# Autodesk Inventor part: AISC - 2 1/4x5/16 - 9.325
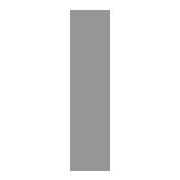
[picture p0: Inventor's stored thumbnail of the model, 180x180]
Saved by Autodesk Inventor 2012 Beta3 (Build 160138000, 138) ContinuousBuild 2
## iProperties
IsCustomPart: 1
Created: 2010-11
Part Number: AISC - 2 1/4x5/16 - 9.325
Material: Steel, Mild
Description: Flat Bar Steel
Document SubType Name: Modeling
Standard: ANSI
Designer: Beta-8540w
Standards Organization: ANSI
Language: en-US
Size Designation: 2 1/4x5/16
Categories: <MemberInstance><Categories><Category DisplayName="Structural Shapes" InternalName="089c4875-fa83-4c05-b084-43b9cc11f5ed" Mnemonic="GRDR"><CategoryParameter Dis
Stock Number: 2 1/4x5/16
Density: 7.86 g/cm^3
_CCFamilyMember: 149
_CCFamilyDisplayName: ANSI AISC (Rectangular) - Flat Bar Steel
_FrameMemberDoc: Frame Member File
_Version: 15.0.0
_GetPNFromCC: 1
G_L: 9.325 in
G_W: 0.313 in
G_H: 2.250 in
Author: Beta-8540w
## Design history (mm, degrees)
node "Start plane"
node "End plane"
node "Driven Length"
  sketch "Sketch3"
    geometry: L1 (0, 0)-(10, 0) reference
    constraints: 2 end point, 1 horizontal
  workplane "Work Plane3"
  sketch "Sketch4"
    geometry: L1 (-2, 0)-(12, 0) reference; L2 (-40.005, 236.864)-(40.005, 236.864) reference
    dimensions: "d9" = 236.86413 distance between parallel lines of L1 L2 (derived)
sketch "Sweep Path"
  geometry: L1 through (25.4, 40.279) direction (1, 0); L2 through (112.121, 127) direction (1, 0); 8 other entities
  constraints: 10 horizontal
node "Orientation Work Plane"
feature "Body" dims "d10" = 0
body "Solid1"
sketch "Sketch"
  geometry: L1 (3.969, -28.575)-(-3.969, -28.575); L2 (-3.969, -28.575)-(-3.969, 28.575); L3 (-3.969, 28.575)-(3.969, 28.575); L4 (3.969, 28.575)-(3.969, -28.575); L5 (-6, 0)-(8, 0); L6 (0, -30)-(0, 40); L7 (0, 54)-(0, -44); L8 (-9.2, 0)-(13.2, 0)
  constraints: 16 end point, 2 collinear, 2 parallel, 1 horizontal, 1 perpendicular
  dimensions: "d0" = 57.15 distance between parallel lines of L3 L1 (= G_W); "d1" = 7.9375 distance between parallel lines of L4 L2 (= G_H); "d4" = 3.96875 distance between parallel lines of L6 L4 (= 0.5 x d1); "d5" = 28.575 distance between parallel lines of L5 L3 (= 0.5 x d0)
other parameters: "G_W" = 57.15 [user parameter; used in 1 equation term], "G_H" = 7.9375 [user parameter; used in 1 equation term], "G_L" = 236.86413 (= d9) [user parameter], "G_OFFSET_START" = 0 [user parameter; used in 1 equation term], "G_OFFSET_END" = 0 [user parameter; used in 1 equation term], "d6" = 0 (computed from G_OFFSET_START), "d7" = 236.86413 (= G_OFFSET_END + B_L), "B_L" = 236.86413 [user parameter; used in 1 equation term], "d8" = 90 deg
